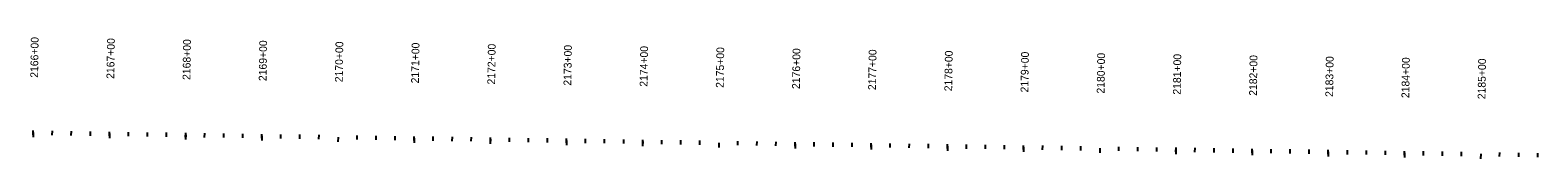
# Model space of a CAD drawing. Extents: x 14295116 to 14303545, y 8637313 to 8653417.
# Drawn here: x 14297107 to 14299086, y 8637595 to 8637755 of the extents above; entities that cross this region are included whole.
import ezdxf

# ---------------------------------------------------------------- set-up
doc = ezdxf.new("R2010")
doc.units = 0
doc.layers.add('Draft_DNC', color=7, linetype='Continuous')
doc.layers.add('G Prop 6 Valve (B1) CELL', color=7, linetype='Continuous')

msp = doc.modelspace()

# ---------------------------------------------------------------- linework, layer by layer
at = {"layer": 'Draft_DNC'}
for p, q in [((14297111.2, 8637629.7), (14297111.1, 8637623.6)), ((14297136.1, 8637626.2), (14297136.2, 8637631.7)), ((14297161.1, 8637625.9), (14297161.2, 8637631.3)), ((14297186.1, 8637625.5), (14297186.2, 8637631)), ((14297211.2, 8637628.2), (14297211.1, 8637622.1)), ((14297236.1, 8637624.8), (14297236.2, 8637630.2)), ((14297261.1, 8637624.4), (14297261.2, 8637629.8)), ((14297286.1, 8637624), (14297286.2, 8637629.5)), ((14297311.2, 8637626.7), (14297311.1, 8637620.6)), ((14297336.1, 8637623.3), (14297336.2, 8637628.7)), ((14297361.1, 8637622.9), (14297361.2, 8637628.4)), ((14297386.1, 8637622.5), (14297386.2, 8637628)), ((14297411.2, 8637625.2), (14297411.1, 8637619.1)), ((14297436.1, 8637621.8), (14297436.2, 8637627.2)), ((14297461.1, 8637621.4), (14297461.2, 8637626.9)), ((14297486.1, 8637621), (14297486.2, 8637626.5)), ((14297511.2, 8637623.7), (14297511.1, 8637617.6)), ((14297536.1, 8637620.3), (14297536.2, 8637625.8)), ((14297561.1, 8637619.9), (14297561.2, 8637625.4)), ((14297586.1, 8637619.6), (14297586.2, 8637625)), ((14297636.1, 8637618.8), (14297636.2, 8637624.3)), ((14297661.1, 8637618.4), (14297661.2, 8637623.9)), ((14297686.1, 8637618.1), (14297686.2, 8637623.5)), ((14297611.1, 8637622.2), (14297611, 8637616.1)), ((14297711.1, 8637620.8), (14297711, 8637614.6)), ((14297736.1, 8637617.3), (14297736.2, 8637622.8)), ((14297761.1, 8637617), (14297761.2, 8637622.4)), ((14297786.1, 8637616.6), (14297786.2, 8637622.1)), ((14297811.1, 8637619.3), (14297811, 8637613.2)), ((14297836.1, 8637615.8), (14297836.2, 8637621.3)), ((14297861.1, 8637615.5), (14297861.1, 8637620.9)), ((14297886.1, 8637615.1), (14297886.1, 8637620.6)), ((14297911.1, 8637617.8), (14297911, 8637611.7)), ((14297936.1, 8637614.4), (14297936.1, 8637619.8)), ((14297961.1, 8637614), (14297961.1, 8637619.5)), ((14297986.1, 8637613.6), (14297986.1, 8637619.1)), ((14298011.1, 8637616.3), (14298011, 8637610.2)), ((14298036, 8637612.9), (14298036.1, 8637618.3)), ((14298061, 8637612.5), (14298061.1, 8637618)), ((14298086, 8637612.1), (14298086.1, 8637617.6)), ((14298111.1, 8637614.8), (14298111, 8637608.7)), ((14298136, 8637611.4), (14298136.1, 8637616.9)), ((14298161, 8637611), (14298161.1, 8637616.5)), ((14298186, 8637610.7), (14298186.1, 8637616.1)), ((14298211.1, 8637613.3), (14298211, 8637607.2)), ((14298236, 8637609.9), (14298236.1, 8637615.4)), ((14298261, 8637609.5), (14298261.1, 8637615)), ((14298286, 8637609.2), (14298286.1, 8637614.6)), ((14298311.1, 8637611.9), (14298311, 8637605.7)), ((14298336, 8637608.4), (14298336.1, 8637613.9)), ((14298361, 8637608.1), (14298361.1, 8637613.5)), ((14298386, 8637607.7), (14298386.1, 8637613.1)), ((14298411.1, 8637610.4), (14298411, 8637604.3)), ((14298436, 8637606.9), (14298436.1, 8637612.4)), ((14298461, 8637606.6), (14298461.1, 8637612)), ((14298486, 8637606.2), (14298486.1, 8637611.7)), ((14298511, 8637608.9), (14298511, 8637602.8)), ((14298536, 8637605.5), (14298536.1, 8637610.9)), ((14298561, 8637605.1), (14298561.1, 8637610.5)), ((14298586, 8637604.7), (14298586.1, 8637610.2)), ((14298611, 8637607.4), (14298610.9, 8637601.3)), ((14298636, 8637604), (14298636.1, 8637609.4)), ((14298661, 8637603.6), (14298661.1, 8637609.1)), ((14298686, 8637603.2), (14298686.1, 8637608.7)), ((14298711, 8637605.9), (14298710.9, 8637599.8)), ((14298736, 8637602.5), (14298736.1, 8637607.9)), ((14298761, 8637602.1), (14298761, 8637607.6)), ((14298786, 8637601.7), (14298786, 8637607.2)), ((14298811, 8637604.4), (14298810.9, 8637598.3)), ((14298836, 8637601), (14298836, 8637606.5)), ((14298861, 8637600.6), (14298861, 8637606.1)), ((14298886, 8637600.3), (14298886, 8637605.7)), ((14298935.9, 8637599.5), (14298936, 8637605)), ((14298960.9, 8637599.1), (14298961, 8637604.6)), ((14298985.9, 8637598.8), (14298986, 8637604.2)), ((14299035.9, 8637598), (14299036, 8637603.5)), ((14298911, 8637602.9), (14298910.9, 8637596.8)), ((14299011, 8637601.5), (14299010.9, 8637595.3)), ((14299060.9, 8637597.7), (14299061, 8637603.1)), ((14299085.9, 8637597.3), (14299086, 8637602.7))]:
    msp.add_line(p, q, dxfattribs=at)
at = {"layer": 'G Prop 6 Valve (B1) CELL'}
for p, q in [((14297111.2, 8637626.6), (14297111.2, 8637632.1)), ((14297211.1, 8637625.1), (14297211.2, 8637630.6)), ((14297311.1, 8637623.6), (14297311.2, 8637629.1)), ((14297411.1, 8637622.2), (14297411.2, 8637627.6)), ((14297511.2, 8637623.7), (14297511.1, 8637617.6)), ((14297611.1, 8637619.2), (14297611.2, 8637624.6)), ((14297711.1, 8637617.7), (14297711.2, 8637623.2)), ((14297811.1, 8637616.2), (14297811.2, 8637621.7)), ((14297911.1, 8637614.7), (14297911.1, 8637620.2)), ((14298011.1, 8637616.3), (14298011, 8637610.2)), ((14298111, 8637611.8), (14298111.1, 8637617.2)), ((14298211, 8637610.3), (14298211.1, 8637615.7)), ((14298311, 8637608.8), (14298311.1, 8637614.3)), ((14298411, 8637607.3), (14298411.1, 8637612.8)), ((14298511, 8637608.9), (14298511, 8637602.8)), ((14298611, 8637604.3), (14298611.1, 8637609.8)), ((14298711, 8637602.9), (14298711.1, 8637608.3)), ((14298811, 8637601.4), (14298811, 8637606.8)), ((14298911, 8637599.9), (14298911, 8637605.3)), ((14299011, 8637601.5), (14299010.9, 8637595.3))]:
    msp.add_line(p, q, dxfattribs=at)

# ---------------------------------------------------------------- texts
at = {"layer": 'Draft_DNC'}
for s, p in [('2166+00', (14297117.4, 8637701.5)), ('2167+00', (14297217.4, 8637700)), ('2168+00', (14297317.3, 8637698.6)), ('2169+00', (14297417.3, 8637697.1)), ('2170+00', (14297517.3, 8637695.6)), ('2171+00', (14297617.3, 8637694.1)), ('2172+00', (14297717.3, 8637692.6)), ('2173+00', (14297817.3, 8637691.1)), ('2174+00', (14297917.3, 8637689.7)), ('2175+00', (14298017.3, 8637688.2)), ('2176+00', (14298117.3, 8637686.7)), ('2177+00', (14298217.2, 8637685.2)), ('2178+00', (14298317.2, 8637683.7)), ('2179+00', (14298417.2, 8637682.2)), ('2180+00', (14298517.2, 8637680.7)), ('2181+00', (14298617.2, 8637679.3)), ('2182+00', (14298717.2, 8637677.8)), ('2183+00', (14298817.2, 8637676.3)), ('2184+00', (14298917.2, 8637674.8)), ('2185+00', (14299017.2, 8637673.3))]:
    msp.add_text(s, height=10.2, rotation=89.1493, dxfattribs=at).set_placement(p)
at = {"layer": 'G Prop 6 Valve (B1) CELL'}
for s, p in [('2170+00', (14297517.3, 8637695.6)), ('2175+00', (14298017.3, 8637688.2)), ('2180+00', (14298517.2, 8637680.7)), ('2185+00', (14299017.2, 8637673.3))]:
    msp.add_text(s, height=10.2, rotation=89.1493, dxfattribs=at).set_placement(p)

doc.saveas('drawing.dxf')
